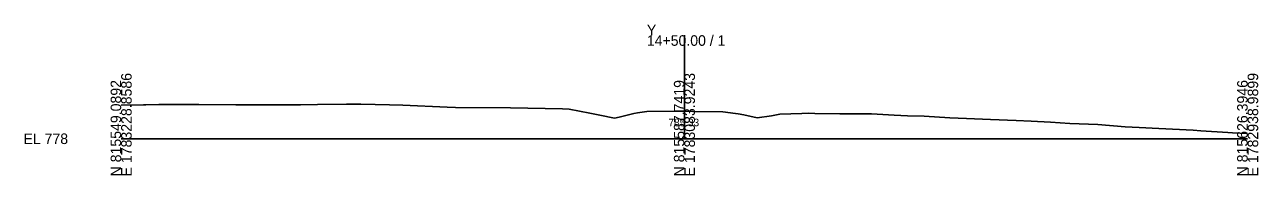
# Model space of a CAD drawing. Extents: x -12583 to 5303, y -44 to 25667.
# Drawn here: x -25.7 to 302.8, y 3990.3 to 4030.3 of the extents above; entities that cross this region are included whole.
import ezdxf

# ---------------------------------------------------------------- set-up
doc = ezdxf.new("R2010")
doc.units = 0
for name, color, linetype in [('Exist Cross Section Cell', 7, 'Continuous'), ('Exist XS Center Line Elevation Label', 7, 'Continuous'), ('Exist XS Ground Line', 7, 'Continuous')]:
    doc.layers.add(name, color=color, linetype=linetype)

msp = doc.modelspace()

# ---------------------------------------------------------------- linework, layer by layer
at = {"layer": 'Exist Cross Section Cell'}
for p, q in [((150, 4000), (150, 4027.5)), ((0, 4000), (150, 4000)), ((150, 4000), (300, 4000))]:
    msp.add_line(p, q, dxfattribs=at)
at = {"layer": 'Exist XS Ground Line'}
for p, q in [((0, 4008.96), (5.98, 4009.06)), ((5.98, 4009.06), (6.55, 4009.06)), ((6.55, 4009.06), (10, 4009.09)), ((10, 4009.09), (16.5, 4009.14)), ((16.5, 4009.14), (17.62, 4009.13)), ((17.62, 4009.13), (20.66, 4009.12)), ((20.66, 4009.12), (30.5, 4009.04)), ((30.5, 4009.04), (38.21, 4009.04)), ((38.21, 4009.04), (47.74, 4009.06)), ((47.74, 4009.06), (52.33, 4009.12)), ((52.33, 4009.12), (59.98, 4009.17)), ((59.98, 4009.17), (63.86, 4009.16)), ((63.86, 4009.16), (71.49, 4009.01)), ((71.49, 4009.01), (75.04, 4008.92)), ((75.04, 4008.92), (86.84, 4008.43)), ((86.84, 4008.43), (89.05, 4008.35)), ((89.05, 4008.35), (103.65, 4008.21)), ((103.65, 4008.21), (117.53, 4007.97)), ((117.53, 4007.97), (119.35, 4007.83)), ((119.35, 4007.83), (124.83, 4006.81)), ((124.83, 4006.81), (127.5, 4006.26)), ((127.5, 4006.26), (131.41, 4005.44)), ((131.41, 4005.44), (132.59, 4005.75)), ((132.59, 4005.75), (136.54, 4006.7)), ((136.54, 4006.7), (137.53, 4006.85)), ((137.53, 4006.85), (139.99, 4007.25)), ((139.99, 4007.25), (147.39, 4007.31)), ((147.39, 4007.31), (150.21, 4007.33)), ((150.21, 4007.33), (152.24, 4007.29)), ((152.24, 4007.29), (160.24, 4007.14)), ((160.24, 4007.14), (163.62, 4006.74)), ((163.62, 4006.74), (164.35, 4006.65)), ((164.35, 4006.65), (165.86, 4006.33)), ((165.86, 4006.33), (169.39, 4005.56)), ((169.39, 4005.56), (173.18, 4006.11)), ((173.18, 4006.11), (175.45, 4006.52)), ((175.45, 4006.52), (181.3, 4006.72)), ((181.3, 4006.72), (182.93, 4006.77)), ((182.93, 4006.77), (184.77, 4006.72)), ((184.77, 4006.72), (191.39, 4006.63)), ((191.39, 4006.63), (194.83, 4006.65)), ((194.83, 4006.65), (199.8, 4006.61)), ((199.8, 4006.61), (205.87, 4006.3)), ((205.87, 4006.3), (209.44, 4006.14)), ((209.44, 4006.14), (213.88, 4005.97)), ((213.88, 4005.97), (220.71, 4005.59)), ((220.71, 4005.59), (225.15, 4005.42)), ((225.15, 4005.42), (231.48, 4005.15)), ((231.48, 4005.15), (238.34, 4004.82)), ((238.34, 4004.82), (242.36, 4004.68)), ((242.36, 4004.68), (247.52, 4004.45)), ((247.52, 4004.45), (252.61, 4004.1)), ((252.61, 4004.1), (260.06, 4003.76)), ((260.06, 4003.76), (267.37, 4003.21)), ((267.37, 4003.21), (271.11, 4003.02)), ((271.11, 4003.02), (276.35, 4002.7)), ((276.35, 4002.7), (285.52, 4002.25)), ((285.52, 4002.25), (287.51, 4002.13)), ((287.51, 4002.13), (294.68, 4001.66)), ((294.68, 4001.66), (295.94, 4001.59)), ((295.94, 4001.59), (300, 4001.39))]:
    msp.add_line(p, q, dxfattribs=at)

# ---------------------------------------------------------------- texts
at = {"layer": 'Exist Cross Section Cell'}
for s, p in [('Y', (140, 4027.5)), ('14+50.00 / 1', (140, 4024.7)), ('EL 778', (-26, 3998.6))]:
    msp.add_text(s, height=2.8, dxfattribs=at).set_placement(p)
for s, p in [('N 815549.0892', (0, 3990)), ('E 1783228.8586', (2.8, 3990)), ('N 815587.7419', (150, 3990)), ('E 1783083.9243', (152.8, 3990)), ('N 815626.3946', (300, 3990)), ('E 1782938.9899', (302.8, 3990))]:
    msp.add_text(s, height=2.8, rotation=90, dxfattribs=at).set_placement(p)
at = {"layer": 'Exist XS Center Line Elevation Label'}
msp.add_text('785.33', height=2, dxfattribs=at).set_placement((145.75, 4003.33))

doc.saveas('drawing.dxf')
